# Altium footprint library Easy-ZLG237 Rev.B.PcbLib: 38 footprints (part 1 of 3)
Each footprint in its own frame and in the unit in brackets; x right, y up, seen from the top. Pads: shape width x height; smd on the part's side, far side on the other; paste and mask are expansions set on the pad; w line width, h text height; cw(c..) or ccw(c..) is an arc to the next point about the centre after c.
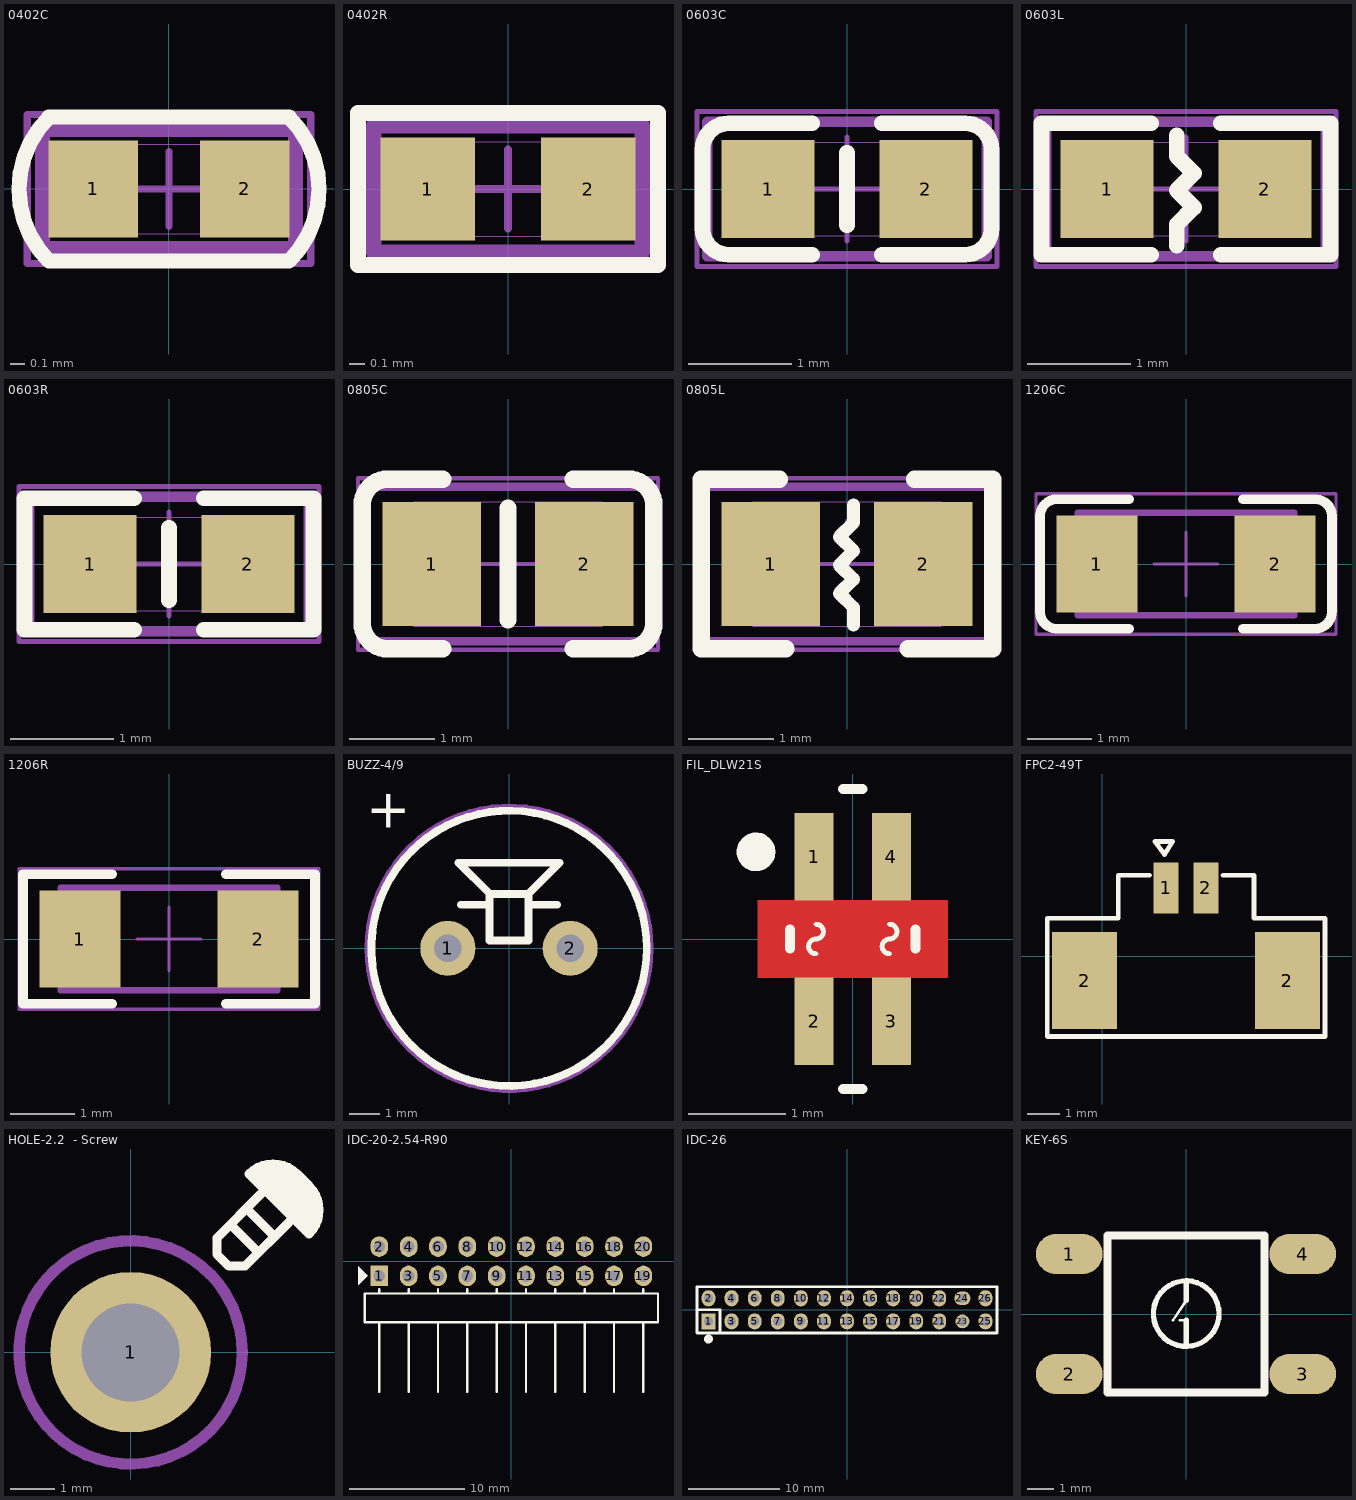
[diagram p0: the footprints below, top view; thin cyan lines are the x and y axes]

## 0402C [mm]
height 0.635
pads (2):
  rect 0.6x0.65 smd mask+0.025: 1(-0.508,0) 2(0.508,0)
Top Overlay:
  lines w0.102: -0.807,0.482 ccw(c-0.326,0) -0.806,-0.483 0.806,-0.483 ccw(c0.326,0) 0.807,0.482 0.806,0.483 -0.806,0.483 -0.807,0.482
Mechanical 15:
  lines w0.1: -0.85,-0.4 0.85,-0.4 0.85,0.4 -0.85,0.4 -0.85,-0.4
Mechanical 16:
  lines w0.001: -0.55,-0.3 0.55,-0.3 0.55,0.3 -0.55,0.3 -0.55,-0.3
  lines w0.05: -0.25,0 0.25,0 ; 0,-0.25 0,0.25 ; -0.95,-0.5 0.95,-0.5 0.95,0.5 -0.95,0.5 -0.95,-0.5
3D body "0402C.stp": height 0.5, standoff 0, extent -0.508,-0.229 0.492,0.271

## 0402R [mm]
height 0.635
pads (2):
  rect 0.6x0.65 smd mask+0.025: 1(-0.508,0) 2(0.508,0)
Top Overlay:
  lines w0.102: -0.95,-0.483 0.95,-0.483 0.95,0.483 -0.95,0.483 -0.95,-0.483
Mechanical 15:
  lines w0.1: -0.85,-0.4 -0.85,0.4 0.85,0.4 0.85,-0.4 -0.85,-0.4
Mechanical 16:
  lines w0.001: -0.55,-0.3 -0.55,0.3 0.55,0.3 0.55,-0.3 -0.55,-0.3
  lines w0.05: -0.25,0 0.25,0 ; 0,-0.25 0,0.25 ; -0.95,-0.5 -0.95,0.5 0.95,0.5 0.95,-0.5 -0.95,-0.5
3D body "R0402.STEP": height 0.35, standoff 0, extent -0.475,-0.254 0.525,0.246

## 0603C [mm]
pads (2):
  rect 0.9x0.95 smd: 1(-0.762,0) 2(0.762,0)
Top Overlay:
  lines w0.152: -0.337,-0.635 -1.143,-0.635 cw(c-1.143,-0.381) -1.397,-0.381 -1.397,0.381 cw(c-1.143,0.381) -1.143,0.635 -0.337,0.635 ; 0,-0.35 0,0.35 ; 0.337,-0.635 1.143,-0.635 ccw(c1.143,-0.381) 1.397,-0.381 1.397,0.381 ccw(c1.143,0.381) 1.143,0.635 0.337,0.635
Mechanical 15:
  lines w0.1: -1.35,-0.65 -1.35,0.65 1.35,0.65 1.35,-0.65 -1.35,-0.65
Mechanical 16:
  lines w0.001: -0.85,-0.45 -0.85,0.45 0.85,0.45 0.85,-0.45 -0.85,-0.45
  lines w0.05: -0.5,0 0.5,0 ; 0,-0.5 0,0.5 ; -1.45,-0.75 -1.45,0.75 1.45,0.75 1.45,-0.75 -1.45,-0.75
3D body "User Library-0603 SMD Capacitor.STEP": height 0.3, standoff 0, extent -0.789,-0.381 0.811,0.419

## 0603L [mm]
pads (2):
  rect 0.9x0.95 smd: 1(-0.762,0) 2(0.762,0)
Top Overlay:
  lines w0.152: -0.337,-0.635 -1.397,-0.635 -1.397,0.635 -0.337,0.635 ; -0.089,-0.546 -0.089,-0.343 0.076,-0.178 -0.089,-0.013 0.076,0.152 -0.089,0.318 -0.089,0.521 ; 0.337,-0.635 1.397,-0.635 1.397,0.635 0.337,0.635
Mechanical 15:
  lines w0.1: -1.35,-0.65 -1.35,0.65 1.35,0.65 1.35,-0.65 -1.35,-0.65
Mechanical 16:
  lines w0.001: -0.85,-0.45 -0.85,0.45 0.85,0.45 0.85,-0.45 -0.85,-0.45
  lines w0.05: -0.5,0 0.5,0 ; 0,-0.5 0,0.5 ; -1.45,-0.75 -1.45,0.75 1.45,0.75 1.45,-0.75 -1.45,-0.75
3D body "User Library-0603 SMD Resistor.STEP": height 0.3, standoff 0, extent -0.8,-0.4 0.8,0.4

## 0603R [mm]
pads (2):
  rect 0.9x0.95 smd: 1(-0.762,0) 2(0.762,0)
Top Overlay:
  lines w0.152: -0.337,-0.635 -1.397,-0.635 -1.397,0.635 -0.337,0.635 ; 0,-0.35 0,0.35 ; 0.337,-0.635 1.397,-0.635 1.397,0.635 0.337,0.635
Mechanical 15:
  lines w0.1: -1.35,-0.65 -1.35,0.65 1.35,0.65 1.35,-0.65 -1.35,-0.65
Mechanical 16:
  lines w0.001: -0.85,-0.45 -0.85,0.45 0.85,0.45 0.85,-0.45 -0.85,-0.45
  lines w0.05: -0.5,0 0.5,0 ; 0,-0.5 0,0.5 ; -1.45,-0.75 -1.45,0.75 1.45,0.75 1.45,-0.75 -1.45,-0.75
3D body "User Library-0603 SMD Resistor.STEP": height 0.3, standoff 0, extent -0.8,-0.4 0.8,0.4

## 0805C [mm]
pads (2):
  rect 1.15x1.45 smd: 1(-0.889,0) 2(0.889,0)
Top Overlay:
  lines w0.2: 0,-0.65 0,0.65
  lines w0.203: -0.762,-0.991 -1.397,-0.991 cw(c-1.397,-0.686) -1.702,-0.686 -1.702,0.686 cw(c-1.397,0.686) -1.397,0.991 -0.762,0.991 ; 0.762,-0.991 1.397,-0.991 ccw(c1.397,-0.686) 1.702,-0.686 1.702,0.686 ccw(c1.397,0.686) 1.397,0.991 0.762,0.991
Mechanical 15:
  lines w0.1: -1.65,-0.9 1.65,-0.9 1.65,0.9 -1.65,0.9 -1.65,-0.9
Mechanical 16:
  lines w0.001: -1.1,-0.725 1.1,-0.725 1.1,0.725 -1.1,0.725 -1.1,-0.725
  lines w0.05: -0.5,0 0.5,0 ; 0,-0.5 0,0.5 ; -1.75,-1 1.75,-1 1.75,1 -1.75,1 -1.75,-1
3D body "SW3dPS-0805 SMD Capacitor.STEP": height 0.78, standoff 0, extent -1,-0.625 1,0.625

## 0805L [mm]
height 1.45
pads (2):
  rect 1.15x1.45 smd: 1(-0.889,0) 2(0.889,0)
Top Overlay:
  lines w0.152: 0.076,-0.711 0.076,-0.508 -0.089,-0.343 0.076,-0.178 -0.089,-0.013 0.076,0.152 -0.089,0.318 0.076,0.483 0.076,0.686
  lines w0.203: -0.787,0.991 -1.702,0.991 -1.702,-0.991 -0.711,-0.991 ; 0.711,-0.991 1.702,-0.991 1.702,0.991 0.787,0.991
Mechanical 15:
  lines w0.1: -1.65,-0.9 -1.65,0.9 1.65,0.9 1.65,-0.9 -1.65,-0.9
Mechanical 16:
  lines w0.001: -1.1,-0.725 -1.1,0.725 1.1,0.725 1.1,-0.725 -1.1,-0.725
  lines w0.05: -0.5,0 0.5,0 ; 0,-0.5 0,0.5 ; -1.75,-1 -1.75,1 1.75,1 1.75,-1 -1.75,-1
3D body "R0805.STEP": height 0.55, standoff 0, extent -1.016,-0.635 0.984,0.625

## 1206C [mil] "元件 长X宽=120X60mil"
height 40
pads (2):
  rect 50x60 smd: 1(-55,0) 2(55,0)
Top Overlay:
  lines w6: -90,29 cw(c-79.5,29.5) -80,40 -35,40 ; -90,30 -90,-30 ccw(c-79.5,-29.5) -79,-40 ; -80,-40 -35,-40 ; 35,-40 79,-40 ; 35,40 80,40 ; 79,40 cw(c79.5,29.5) 90,30 90,-29 cw(c79.5,-29.5) 80,-40
Mechanical 15:
  lines w3.94: -66.93,-31.5 66.93,-31.5 66.93,31.5 -66.93,31.5 -66.93,-31.5
Mechanical 16:
  lines w0.04: -66.93,-31.5 66.93,-31.5 66.93,31.5 -66.93,31.5 -66.93,-31.5
  lines w1.97: -19.68,0 19.68,0 ; 0,-19.68 0,19.68 ; -92.52,-43.31 92.52,-43.31 92.52,43.31 -92.52,43.31 -92.52,-43.31
3D body "1206c.stp": height 39.37, standoff 0, extent -62,-32 63.98,30.99

## 1206R [mil] "元件 长X宽=120X60mil"
height 40
pads (2):
  rect 50x60 smd: 1(-55,0) 2(55,0)
Top Overlay:
  lines w6: -35,-40 -90,-40 -90,40 -35,40 ; 35,-40 90,-40 90,40 35,40
Mechanical 15:
  lines w3.94: -66.93,-31.5 66.93,-31.5 66.93,31.5 -66.93,31.5 -66.93,-31.5
Mechanical 16:
  lines w0.04: -66.93,-31.5 66.93,-31.5 66.93,31.5 -66.93,31.5 -66.93,-31.5
  lines w1.97: -19.68,0 19.68,0 ; 0,-19.68 0,19.68 ; -92.52,-43.31 92.52,-43.31 92.52,43.31 -92.52,43.31 -92.52,-43.31
3D body "R1206.STEP": height 23.62, standoff 0, extent -62.93,-31.5 63.06,31.5

## BUZZ-4/9 [mm] "工制单位"
height 5
pads (2):
  round 1.8 hole 0.9: 1(-2,0) 2(2,0)
Top Overlay:
  circle w0.254: c0,0 r4.5
  lines w0.254: -1.575,1.424 -0.635,1.424 ; 0.635,1.424 1.575,1.424 ; -0.635,1.778 0.635,1.778 ; -0.635,1.778 -1.651,2.794 1.651,2.794 0.635,1.778 ; -0.635,1.778 -0.635,0.254 0.635,0.254 0.635,1.778
  text "+" at -4.667,3.937 h1.27
Mechanical 15:
  circle w0.254: c0,0 r4.6

## FIL_DLW21S [mm] "共模扼流圈"
height 1.2
pads (4):
  rect 0.4x0.9 smd paste-0.2: 1(-0.4,0.85) 2(-0.4,-0.85) 3(0.4,-0.85) 4(0.4,0.85)
Top Layer:
  pour cut-out: -0.981,0.4 0.981,0.4 0.981,-0.4 -0.981,-0.4
Top Overlay:
  circle w0.2: c-1,0.9 r0.1
  lines w0.051: -0.38,-0.152 cw(c-0.38,-0.076) -0.456,-0.076 cw(c-0.38,-0.076) -0.38,0 ccw(c-0.38,0.076) -0.304,0.076 ccw(c-0.38,0.076) -0.38,0.152 ; 0.38,-0.152 cw(c0.38,-0.076) 0.304,-0.076 cw(c0.38,-0.076) 0.38,0 ccw(c0.38,0.076) 0.456,0.076 ccw(c0.38,0.076) 0.38,0.152
  lines w0.102: -0.65,-0.1 -0.65,0.1 ; -0.1,-1.55 0.1,-1.55 ; -0.1,1.55 0.1,1.55 ; 0.65,-0.1 0.65,0.1
Top Paste:
  region: 0.6,0.4 0.6,1.3 0.25,1.3 0.25,0.4
  region: 0.6,-1.3 0.6,-0.4 0.25,-0.4 0.25,-1.3
  region: -0.6,-0.4 -0.6,-1.3 -0.25,-1.3 -0.25,-0.4
  region: -0.6,1.3 -0.6,0.4 -0.25,0.4 -0.25,1.3

## FPC2-49T [mil]
pads (4):
  rect 31x63 smd: 1(78.58,84.25) 2(127.79,84.25)
  rect 80x120 smd: 2(-21.82,-29.93) 2(228.18,-29.93)
Top Overlay:
  lines w5.91: 58.1,99.99 19.72,99.99 19.72,46.85 -67.88,46.85 -67.88,-98.82 274.64,-98.82 274.64,46.85 187.04,46.85 187.04,99.99 148.66,99.99 ; 64.99,141.33 86.65,141.33 76.81,125.59 64.99,141.33

## HOLE-2.2  - Screw [mm]
pads (1):
  round 3.6 hole 2.2: 1(0,0)
Top Overlay:
  region: 2.649,3.996 3.996,2.649 4.046,2.699 4.125,2.817 4.179,2.948 4.207,3.086 4.207,3.157 4.207,3.407 4.207,3.433 4.197,3.484 4.177,3.532 4.148,3.575 4.13,3.593 3.812,3.911 3.74,3.983 3.569,4.097 3.38,4.176 3.179,4.216 3.076,4.216 3.039,4.216 2.999,4.216 2.919,4.2 2.844,4.169 2.777,4.124 2.748,4.095
  lines w0.203: 2.288,2.812 2.827,2.273 ; 2.647,3.171 3.186,2.632 ; 2.919,3.547 1.931,2.559 1.931,2.2 2.2,1.931 2.559,1.931 3.547,2.919 ; 2.649,3.996 cw(c3.188,3.457) 3.727,3.996 3.996,3.727 cw(c3.457,3.188) 3.996,2.649 2.649,3.996
Mechanical 15:
  circle w0.254: c0,0 r2.5

## IDC-20-2.54-R90 [mil] "Connector; Header; 10x2 Position"
pads (20):
  rect 60x70 hole 40: 1(-450,-50)
  oval 60x70 hole 40: 2(-450,50) 3(-350,-50) 4(-350,50) 5(-250,-50) 6(-250,50) 7(-150,-50) 8(-150,50) 9(-50,-50) 10(-50,50) 11(50,-50) 12(50,50) 13(150,-50) 14(150,50) 15(250,-50) 16(250,50) 17(350,-50) 18(350,50) 19(450,-50) 20(450,50)
Top Overlay:
  region: -490,-50 -522.5,-17.5 -522.5,-82.5
  lines w8: -450,-444.49 -450,-208.27 ; -450,-109.84 -450,-94.49 ; -350,-444.49 -350,-208.27 ; -350,-109.84 -350,-94.49 ; -250,-444.49 -250,-208.27 ; -250,-109.84 -250,-94.49 ; -150,-444.49 -150,-208.27 ; -150,-109.84 -150,-94.49 ; -50,-444.49 -50,-208.27 ; -50,-109.84 -50,-94.49 ; 50,-444.49 50,-208.27 ; 50,-109.84 50,-94.49 ; 150,-444.49 150,-208.27 ; 150,-109.84 150,-94.49 ; 250,-444.49 250,-208.27 ; 250,-109.84 250,-94.49 ; 350,-444.49 350,-208.27 ; 350,-109.84 350,-94.49 ; 450,-444.49 450,-208.27 ; 450,-109.84 450,-94.49 ; -500,-208.27 500,-208.27 500,-109.84 -500,-109.84 -500,-208.27

## IDC-26 [mil]
height 118.11
pads (26):
  rect 60x70 hole 40: 1(-600,-50)
  oval 60x70 hole 40: 2(-600,50) 3(-500,-50) 4(-500,50) 5(-400,-50) 6(-400,50) 7(-300,-50) 8(-300,50) 9(-200,-50) 10(-200,50) 11(-100,-50) 12(-100,50) 13(0,-50) 14(0,50) 15(100,-50) 16(100,50) 17(200,-50) 18(200,50) 19(300,-50) 20(300,50) 21(400,-50) 22(400,50) 25(600,-50) 26(600,50)
  round 60 / inner oval 70x60 / far side oval 70x60 hole 40: 23(500,-50)
  oval 70x60 hole 40: 24(500,50)
Top Overlay:
  circle w20: c-600.22,-127 r9.22
  lines w12: -650,0 -550,0 -550,-100 ; -650,-100 -650,100 650,100 650,-100 -650,-100
3D body: height 298.43, standoff -115.75, extent 550,0 650,100
3D body: height 298.43, standoff -115.75, extent 550,-100 650,0
3D body: height 298.43, standoff -115.75, extent 350,0 450,100
3D body: height 298.43, standoff -115.75, extent 450,0 550,100
3D body: height 298.43, standoff -115.75, extent 350,-100 450,0
3D body: height 298.43, standoff -115.75, extent 450,-100 550,0
3D body: height 298.43, standoff -115.75, extent 150,0 250,100
3D body: height 298.43, standoff -115.75, extent 250,0 350,100
3D body: height 298.43, standoff -115.75, extent 150,-100 250,0
3D body: height 298.43, standoff -115.75, extent 250,-100 350,0
3D body: height 298.43, standoff -115.75, extent -50,0 50,100
3D body: height 298.43, standoff -115.75, extent 50,0 150,100
3D body: height 298.43, standoff -115.75, extent -50,-100 50,0
3D body: height 298.43, standoff -115.75, extent 50,-100 150,0
3D body: height 298.43, standoff -115.75, extent -250,0 -150,100
3D body: height 298.43, standoff -115.75, extent -150,0 -50,100
3D body: height 298.43, standoff -115.75, extent -250,-100 -150,0
3D body: height 298.43, standoff -115.75, extent -150,-100 -50,0
3D body: height 298.43, standoff -115.75, extent -450,0 -350,100
3D body: height 298.43, standoff -115.75, extent -350,0 -250,100
3D body: height 298.43, standoff -115.75, extent -450,-100 -350,0
3D body: height 298.43, standoff -115.75, extent -350,-100 -250,0
3D body: height 298.43, standoff -115.75, extent -650,0 -550,100
3D body: height 298.43, standoff -115.75, extent -550,0 -450,100
3D body: height 298.43, standoff -115.75, extent -650,-100 -550,0
3D body: height 298.43, standoff -115.75, extent -550,-100 -450,0

## KEY-6S [mil]
height 120
pads (4):
  oval 100x60 smd: 1(-175,90) 2(-175,-90) 3(175,-90) 4(175,90)
Top Overlay:
  circle w8: c0.27,0.61 r49.21
  lines w4: -19.42,-9.24 0.27,20.29 ; -9.57,-9.24 0.27,-9.24
  lines w8: 0.27,-48.61 0.27,-9.24 ; 0.27,20.29 0.27,49.82
  lines w12: -118.11,-118.11 118.11,-118.11 118.11,118.11 -118.11,118.11 -118.11,-118.11
3D body: height 267.87, standoff 2.13, extent -200.64,-122.05 200.65,122.05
